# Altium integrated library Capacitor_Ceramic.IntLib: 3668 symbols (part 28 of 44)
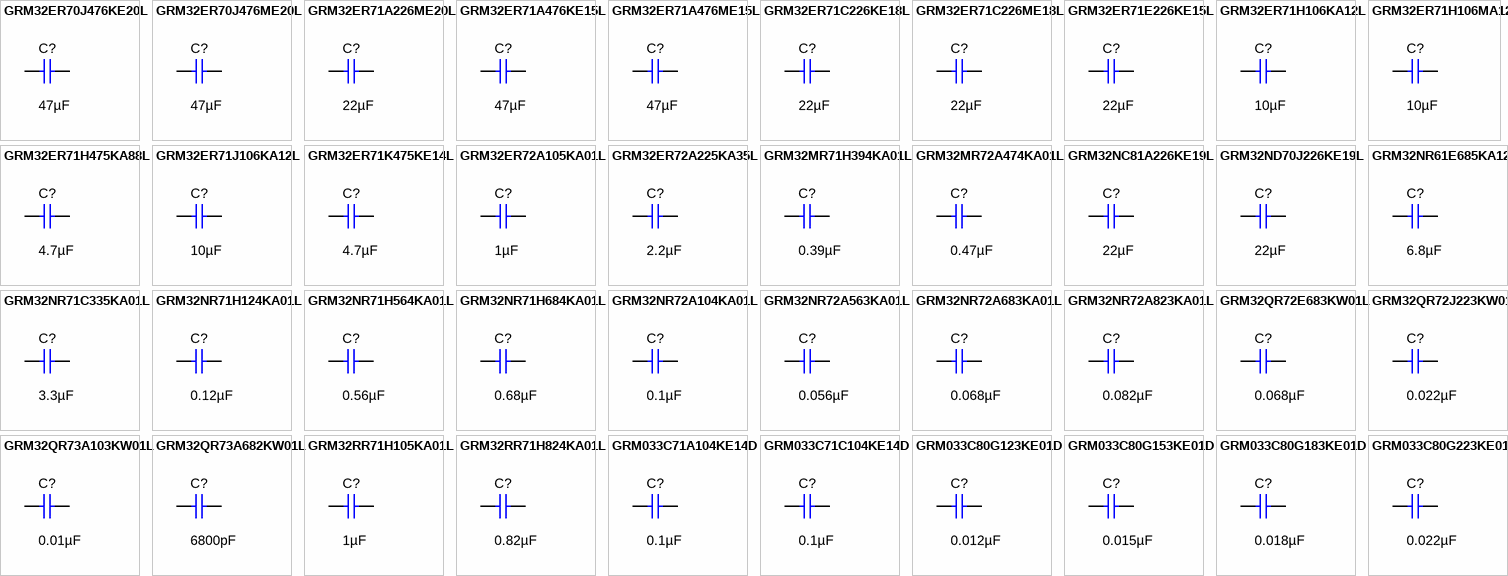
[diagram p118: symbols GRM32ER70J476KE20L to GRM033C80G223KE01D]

## GRM32ER71A476KE15L
designator C?  ValueDisplayed: 47µF  (hidden comment: GRM32ER71A476KE15L)
CAP, CERM, 47 µF, 10 V,+/- 10%, X7R, 1210; Manufacturer: MuRata; Polarized: N; CompType: Capacitor; Value: 47uF; U/M: EA; Cap_F: 0.000047; Tolerance_%: 10; Value2: 10V; TaMin_C: -55; TaMax_C: 125; Cap_Case: 1210; SizeArea_mm2: 8; SizeAreaWB_mm2: 14.7; SizeX_mm: 3.2; SizeY_mm: 2.5; SizeZ_mm: 2.7; AEC Category: Q200; Green_Lifecycle: Active; Green_REACh: Passed
signal-integrity model Cap
simulation model Cap
footprint 1210_270
footprint 1210_270M
footprint 1210_270L
pins: 1, 2

## GRM32ER71A476ME15L
designator C?  ValueDisplayed: 47µF  (hidden comment: GRM32ER71A476ME15L)
CAP, CERM, 47 µF, 10 V,+/- 20%, X7R, 1210; Manufacturer: MuRata; Polarized: N; CompType: Capacitor; Value: 47uF; U/M: EA; Cap_F: 0.000047; Tolerance_%: 20; VDC_V: 10; Value2: 10V; TaMin_C: -55; TaMax_C: 125; Cap_Case: 1210; SizeArea_mm2: 8; SizeAreaWB_mm2: 14.7; SizeX_mm: 3.2; SizeY_mm: 2.5; SizeZ_mm: 2.7; AEC Category: Q200; Green_Lifecycle: Active; Green_REACh: Passed
signal-integrity model Cap
simulation model Cap
footprint 1210_270
footprint 1210_270M
footprint 1210_270L
pins: 1, 2

## GRM32ER71C226KE18L
designator C?  ValueDisplayed: 22µF  (hidden comment: GRM32ER71C226KE18L)
CAP, CERM, 22 µF, 16 V,+/- 10%, X7R, 1210; Manufacturer: MuRata; Polarized: N; CompType: Capacitor; Value: 22uF; U/M: EA; Cap_F: 0.000022; Tolerance_%: 10; ESR_ohm: 0.003; Value1: 0.003 ohm; VDC_V: 16; Value2: 16V; TaMin_C: -55; TaMax_C: 125; Cap_Case: 1210; SizeArea_mm2: 8; SizeAreaWB_mm2: 14.7; SizeX_mm: 3.2; SizeY_mm: 2.5; SizeZ_mm: 2.7; AEC Category: Q200; Green_Lifecycle: Not Set; Green_REACh: Incomplete
signal-integrity model Cap
simulation model Cap
footprint 1210_270
footprint 1210_270M
footprint 1210_270L
pins: 1, 2

## GRM32ER71C226ME18L
designator C?  ValueDisplayed: 22µF  (hidden comment: GRM32ER71C226ME18L)
CAP, CERM, 22 µF, 16 V,+/- 20%, X7R, 1210; Manufacturer: MuRata; Polarized: N; CompType: Capacitor; Value: 22uF; U/M: EA; Cap_F: 0.000022; Tolerance_%: 20; ESR_ohm: 0.003; Value1: 0.003 ohm; VDC_V: 16; Value2: 16V; IRMS_A: 3.2; TaMin_C: -55; TaMax_C: 125; Cap_Case: 1210; SizeArea_mm2: 8; SizeAreaWB_mm2: 14.7; SizeY_mm: 2.5; SizeZ_mm: 2.7; AEC Category: Q200; Green_Lifecycle: Not Set; Green_REACh: Incomplete
signal-integrity model Cap
simulation model Cap
footprint 1210_270
footprint 1210_270M
footprint 1210_270L
pins: 1, 2

## GRM32ER71E226KE15L
designator C?  ValueDisplayed: 22µF  (hidden comment: GRM32ER71E226KE15L)
CAP, CERM, 22 µF, 25 V,+/- 10%, X7R, 1210; Manufacturer: MuRata; Polarized: N; CompType: Capacitor; Value: 22uF; U/M: EA; Cap_F: 0.000022; Tolerance_%: 10; ESR_ohm: 0.002334; Value1: 0.002334 ohm; VDC_V: 25; Value2: 25V; IRMS_A: 3.832999; TaMin_C: -55; TaMax_C: 125; Cap_Case: 1210; SizeArea_mm2: 8; SizeAreaWB_mm2: 14.7; SizeX_mm: 3.2; SizeY_mm: 2.5; SizeZ_mm: 2.7; AEC Category: Q200; Green_Lifecycle: Active; Green_REACh: Passed
signal-integrity model Cap
simulation model Cap
footprint 1210_270
footprint 1210_270M
footprint 1210_270L
pins: 1, 2

## GRM32ER71H106KA12L
designator C?  ValueDisplayed: 10µF  (hidden comment: GRM32ER71H106KA12L)
CAP, CERM, 10 µF, 50 V,+/- 10%, X7R, 1210; Manufacturer: MuRata; Polarized: N; CompType: Capacitor; Value: 10uF; U/M: EA; Cap_F: 0.00001; Tolerance_%: 10; VDC_V: 50; Value2: 50V; TaMin_C: -55; TaMax_C: 125; Cap_Case: 1210; SizeArea_mm2: 8; SizeAreaWB_mm2: 14.7; SizeX_mm: 3.2; SizeY_mm: 2.5; SizeZ_mm: 2.7; AEC Category: Q200; Green_Lifecycle: Active; Green_REACh: Passed
signal-integrity model Cap
simulation model Cap
footprint 1210_270
footprint 1210_270M
footprint 1210_270L
pins: 1, 2

## GRM32ER71H106MA12
designator C?  ValueDisplayed: 10µF  (hidden comment: GRM32ER71H106MA12)
CAP, CERM, 10 µF, 50 V,+/- 20%, X7R, 1210; Manufacturer: MuRata; Polarized: N; CompType: Capacitor; Value: 10uF; U/M: EA; Cap_F: 0.00001; Tolerance_%: 20; VDC_V: 50; Value2: 50V; TaMin_C: -55; TaMax_C: 125; Cap_Case: 1210; SizeArea_mm2: 8; SizeAreaWB_mm2: 14.7; SizeX_mm: 3.2; SizeY_mm: 2.5; SizeZ_mm: 2.7; AEC Category: Q200
signal-integrity model Cap
simulation model Cap
footprint 1210_270
footprint 1210_270M
footprint 1210_270L
pins: 1, 2

## GRM32ER71H475KA88L
designator C?  ValueDisplayed: 4.7µF  (hidden comment: GRM32ER71H475KA88L)
CAP, CERM, 4.7 µF, 50 V,+/- 10%, X7R, 1210; Manufacturer: MuRata; Polarized: N; CompType: Capacitor; Value: 4.7uF; U/M: EA; Cap_F: 0.0000047; Tolerance_%: 10; ESR_ohm: 0.002; Value1: 0.002 ohm; VDC_V: 50; Value2: 50V; TaMin_C: -55; TaMax_C: 125; Cap_Case: 1210; SizeArea_mm2: 8; SizeAreaWB_mm2: 14.7; SizeX_mm: 3.2; SizeY_mm: 2.5; SizeZ_mm: 2.7; AEC Category: Q200; Green_Lifecycle: Active; Green_REACh: Passed
signal-integrity model Cap
simulation model Cap
footprint 1210_270
footprint 1210_270M
footprint 1210_270L
pins: 1, 2

## GRM32ER71J106KA12L
designator C?  ValueDisplayed: 10µF  (hidden comment: GRM32ER71J106KA12L)
CAP, CERM, 10 µF, 63 V,+/- 10%, X7R, 1210; Manufacturer: MuRata; Polarized: N; CompType: Capacitor; Value: 10uF; U/M: EA; Cap_F: 0.00001; Tolerance_%: 10; VDC_V: 63; Value2: 63V; TaMin_C: -55; TaMax_C: 125; Cap_Case: 1210; SizeArea_mm2: 8; SizeAreaWB_mm2: 14.7; SizeX_mm: 3.2; SizeY_mm: 2.5; SizeZ_mm: 2.7; AEC Category: Q200; Green_Lifecycle: Active; Green_REACh: Passed
signal-integrity model Cap
simulation model Cap
footprint 1210_270
footprint 1210_270M
footprint 1210_270L
pins: 1, 2

## GRM32ER71K475KE14L
designator C?  ValueDisplayed: 4.7µF  (hidden comment: GRM32ER71K475KE14L)
CAP, CERM, 4.7 µF, 80 V,+/- 10%, X7R, 1210; Manufacturer: MuRata; Polarized: N; CompType: Capacitor; Value: 4.7uF; U/M: EA; Cap_F: 0.0000047; Tolerance_%: 10; VDC_V: 80; Value2: 80V; TaMin_C: -55; TaMax_C: 125; Cap_Case: 1210; SizeArea_mm2: 8; SizeAreaWB_mm2: 14.7; SizeX_mm: 3.2; SizeY_mm: 2.5; SizeZ_mm: 2.7; AEC Category: Q200
signal-integrity model Cap
simulation model Cap
footprint 1210_270
footprint 1210_270M
footprint 1210_270L
pins: 1, 2

## GRM32ER72A105KA01L
designator C?  ValueDisplayed: 1µF  (hidden comment: GRM32ER72A105KA01L)
CAP, CERM, 1 µF, 100 V,+/- 10%, X7R, 1210; Manufacturer: MuRata; Polarized: N; CompType: Capacitor; Value: 1uF; U/M: EA; Cap_F: 0.000001; Tolerance_%: 10; VDC_V: 100; Value2: 100V; TaMin_C: -55; TaMax_C: 125; Cap_Case: 1210; SizeArea_mm2: 8; SizeAreaWB_mm2: 14.7; SizeX_mm: 3.2; SizeY_mm: 2.5; SizeZ_mm: 2.7; AEC Category: Q200; Green_Lifecycle: Active; Green_REACh: Passed
signal-integrity model Cap
simulation model Cap
footprint 1210_270
footprint 1210_270M
footprint 1210_270L
pins: 1, 2

## GRM32ER72A225KA35L
designator C?  ValueDisplayed: 2.2µF  (hidden comment: GRM32ER72A225KA35L)
CAP, CERM, 2.2 µF, 100 V,+/- 10%, X7R, 1210; Manufacturer: MuRata; Polarized: N; CompType: Capacitor; Value: 2.2uF; U/M: EA; Cap_F: 0.0000022; Tolerance_%: 10; ESR_ohm: 0.007; Value1: 0.007 ohm; VDC_V: 100; Value2: 100V; IRMS_A: 4.4; TaMin_C: -55; TaMax_C: 125; Cap_Case: 1210; SizeArea_mm2: 8; SizeAreaWB_mm2: 14.7; SizeX_mm: 3.2; SizeY_mm: 2.5; SizeZ_mm: 2.7; AEC Category: Q200; Green_Lifecycle: Active; Green_REACh: Passed
signal-integrity model Cap
simulation model Cap
footprint 1210_270
footprint 1210_270M
footprint 1210_270L
pins: 1, 2

## GRM32MR71H394KA01L
designator C?  ValueDisplayed: 0.39µF  (hidden comment: GRM32MR71H394KA01L)
CAP, CERM, 0.39 µF, 50 V,+/- 10%, X7R, 1210; Manufacturer: MuRata; Polarized: N; CompType: Capacitor; Value: 0.39uF; U/M: EA; Cap_F: 0.00000039; Tolerance_%: 10; VDC_V: 50; Value2: 50V; TaMin_C: -55; TaMax_C: 125; Cap_Case: 1210; SizeArea_mm2: 8; SizeAreaWB_mm2: 14.7; SizeX_mm: 3.2; SizeY_mm: 2.5; SizeZ_mm: 1.35; AEC Category: Q200
signal-integrity model Cap
simulation model Cap
footprint 1210
footprint 1210M
footprint 1210L
pins: 1, 2

## GRM32MR72A474KA01L
designator C?  ValueDisplayed: 0.47µF  (hidden comment: GRM32MR72A474KA01L)
CAP, CERM, 0.47 µF, 100 V,+/- 10%, X7R, 1210; Manufacturer: MuRata; Polarized: N; CompType: Capacitor; Value: 0.47uF; U/M: EA; Cap_F: 0.00000047; Tolerance_%: 10; VDC_V: 100; Value2: 100V; TaMin_C: -55; TaMax_C: 125; Cap_Case: 1210; SizeArea_mm2: 8; SizeAreaWB_mm2: 14.7; SizeX_mm: 3.2; SizeY_mm: 2.5; SizeZ_mm: 1.35; AEC Category: Q200
signal-integrity model Cap
simulation model Cap
footprint 1210
footprint 1210M
footprint 1210L
pins: 1, 2

## GRM32NC81A226KE19L
designator C?  ValueDisplayed: 22µF  (hidden comment: GRM32NC81A226KE19L)
CAP, CERM, 22 µF, 10 V,+/- 10%, X6S, 1210; Manufacturer: MuRata; Polarized: N; CompType: Capacitor; Value: 22uF; U/M: EA; Cap_F: 0.000022; Tolerance_%: 10; Value2: 10V; TaMin_C: -55; TaMax_C: 105; Cap_Case: 1210; SizeArea_mm2: 8; SizeAreaWB_mm2: 14.7; SizeX_mm: 3.2; SizeY_mm: 2.5; SizeZ_mm: 1.5; AEC Category: Q200
signal-integrity model Cap
simulation model Cap
footprint 1210_150
footprint 1210_150M
footprint 1210_150L
pins: 1, 2

## GRM32ND70J226KE19L
designator C?  ValueDisplayed: 22µF  (hidden comment: GRM32ND70J226KE19L)
CAP, CERM, 22 µF, 6.3 V,+/- 10%, X7T, 1210; Manufacturer: MuRata; Polarized: N; CompType: Capacitor; Value: 22uF; U/M: EA; Cap_F: 0.000022; Tolerance_%: 10; VDC_V: 6.3; Value2: 6.3V; TaMin_C: -55; TaMax_C: 125; Cap_Case: 1210; SizeArea_mm2: 8; SizeAreaWB_mm2: 14.7; SizeX_mm: 3.2; SizeY_mm: 2.5; SizeZ_mm: 1.5; AEC Category: Q200
signal-integrity model Cap
simulation model Cap
footprint 1210_150
footprint 1210_150M
footprint 1210_150L
pins: 1, 2

## GRM32NR61E685KA12L
designator C?  ValueDisplayed: 6.8µF  (hidden comment: GRM32NR61E685KA12L)
CAP, CERM, 6.8 µF, 25 V,+/- 10%, X5R, 1210; Manufacturer: MuRata; Polarized: N; CompType: Capacitor; Value: 6.8uF; U/M: EA; Cap_F: 0.0000068; Tolerance_%: 10; VDC_V: 25; Value2: 25V; TaMin_C: -55; TaMax_C: 85; Cap_Case: 1210; SizeArea_mm2: 8; SizeAreaWB_mm2: 14.7; SizeX_mm: 3.2; SizeY_mm: 2.5; SizeZ_mm: 1.5; AEC Category: Q200
signal-integrity model Cap
simulation model Cap
footprint 1210_150
footprint 1210_150M
footprint 1210_150L
pins: 1, 2

## GRM32NR71C335KA01L
designator C?  ValueDisplayed: 3.3µF  (hidden comment: GRM32NR71C335KA01L)
CAP, CERM, 3.3 µF, 16 V,+/- 10%, X7R, 1210; Manufacturer: MuRata; Polarized: N; CompType: Capacitor; Value: 3.3uF; U/M: EA; Cap_F: 0.0000033; Tolerance_%: 10; VDC_V: 16; Value2: 16V; TaMin_C: -55; TaMax_C: 125; Cap_Case: 1210; SizeArea_mm2: 8; SizeAreaWB_mm2: 14.7; SizeX_mm: 3.2; SizeY_mm: 2.5; SizeZ_mm: 1.5; AEC Category: Q200
signal-integrity model Cap
simulation model Cap
footprint 1210_150
footprint 1210_150M
footprint 1210_150L
pins: 1, 2

## GRM32NR71H124KA01L
designator C?  ValueDisplayed: 0.12µF  (hidden comment: GRM32NR71H124KA01L)
CAP, CERM, 0.12 µF, 50 V,+/- 10%, X7R, 1210; Manufacturer: MuRata; Polarized: N; CompType: Capacitor; Value: 0.12uF; U/M: EA; Cap_F: 0.00000012; Tolerance_%: 10; VDC_V: 50; Value2: 50V; TaMin_C: -55; TaMax_C: 125; Cap_Case: 1210; SizeArea_mm2: 8; SizeAreaWB_mm2: 14.7; SizeX_mm: 3.2; SizeY_mm: 2.5; SizeZ_mm: 1.5; AEC Category: Q200
signal-integrity model Cap
simulation model Cap
footprint 1210_150
footprint 1210_150M
footprint 1210_150L
pins: 1, 2

## GRM32NR71H564KA01L
designator C?  ValueDisplayed: 0.56µF  (hidden comment: GRM32NR71H564KA01L)
CAP, CERM, 0.56 µF, 50 V,+/- 10%, X7R, 1210; Manufacturer: MuRata; Polarized: N; CompType: Capacitor; Value: 0.56uF; U/M: EA; Cap_F: 0.00000056; Tolerance_%: 10; VDC_V: 50; Value2: 50V; TaMin_C: -55; TaMax_C: 125; Cap_Case: 1210; SizeArea_mm2: 8; SizeAreaWB_mm2: 14.7; SizeX_mm: 3.2; SizeY_mm: 2.5; SizeZ_mm: 1.5; AEC Category: Q200
signal-integrity model Cap
simulation model Cap
footprint 1210_150
footprint 1210_150M
footprint 1210_150L
pins: 1, 2

## GRM32NR71H684KA01L
designator C?  ValueDisplayed: 0.68µF  (hidden comment: GRM32NR71H684KA01L)
CAP, CERM, 0.68 µF, 50 V,+/- 10%, X7R, 1210; Manufacturer: MuRata; Polarized: N; CompType: Capacitor; Value: 0.68uF; U/M: EA; Cap_F: 0.00000068; Tolerance_%: 10; VDC_V: 50; Value2: 50V; TaMin_C: -55; TaMax_C: 125; Cap_Case: 1210; SizeArea_mm2: 8; SizeAreaWB_mm2: 14.7; SizeX_mm: 3.2; SizeY_mm: 2.5; SizeZ_mm: 1.5; AEC Category: Q200
signal-integrity model Cap
simulation model Cap
footprint 1210_150
footprint 1210_150M
footprint 1210_150L
pins: 1, 2

## GRM32NR72A104KA01L
designator C?  ValueDisplayed: 0.1µF  (hidden comment: GRM32NR72A104KA01L)
CAP, CERM, 0.1 µF, 100 V,+/- 10%, X7R, 1210; Manufacturer: MuRata; Polarized: N; CompType: Capacitor; Value: 0.1uF; U/M: EA; Cap_F: 0.0000001; Tolerance_%: 10; VDC_V: 100; Value2: 100V; TaMin_C: -55; TaMax_C: 125; Cap_Case: 1210; SizeArea_mm2: 8; SizeAreaWB_mm2: 14.7; SizeX_mm: 3.2; SizeY_mm: 2.5; SizeZ_mm: 1.5; AEC Category: Q200; Green_Lifecycle: Active; Green_REACh: Passed
signal-integrity model Cap
simulation model Cap
footprint 1210_150
footprint 1210_150M
footprint 1210_150L
pins: 1, 2

## GRM32NR72A563KA01L
designator C?  ValueDisplayed: 0.056µF  (hidden comment: GRM32NR72A563KA01L)
CAP, CERM, 0.056 µF, 100 V,+/- 10%, X7R, 1210; Manufacturer: MuRata; Polarized: N; CompType: Capacitor; Value: 0.056uF; U/M: EA; Cap_F: 0.000000056; Tolerance_%: 10; VDC_V: 100; Value2: 100V; TaMin_C: -55; TaMax_C: 125; Cap_Case: 1210; SizeArea_mm2: 8; SizeAreaWB_mm2: 14.7; SizeX_mm: 3.2; SizeY_mm: 2.5; SizeZ_mm: 1.5; AEC Category: Q200
signal-integrity model Cap
simulation model Cap
footprint 1210_150
footprint 1210_150M
footprint 1210_150L
pins: 1, 2

## GRM32NR72A683KA01L
designator C?  ValueDisplayed: 0.068µF  (hidden comment: GRM32NR72A683KA01L)
CAP, CERM, 0.068 µF, 100 V,+/- 10%, X7R, 1210; Manufacturer: MuRata; Polarized: N; CompType: Capacitor; Value: 0.068uF; U/M: EA; Cap_F: 0.000000068; Tolerance_%: 10; VDC_V: 100; Value2: 100V; TaMin_C: -55; TaMax_C: 125; Cap_Case: 1210; SizeArea_mm2: 8; SizeAreaWB_mm2: 14.7; SizeX_mm: 3.2; SizeY_mm: 2.5; SizeZ_mm: 1.5; AEC Category: Q200
signal-integrity model Cap
simulation model Cap
footprint 1210_150
footprint 1210_150M
footprint 1210_150L
pins: 1, 2

## GRM32NR72A823KA01L
designator C?  ValueDisplayed: 0.082µF  (hidden comment: GRM32NR72A823KA01L)
CAP, CERM, 0.082 µF, 100 V,+/- 10%, X7R, 1210; Manufacturer: MuRata; Polarized: N; CompType: Capacitor; Value: 0.082uF; U/M: EA; Cap_F: 0.000000082; Tolerance_%: 10; VDC_V: 100; Value2: 100V; TaMin_C: -55; TaMax_C: 125; Cap_Case: 1210; SizeArea_mm2: 8; SizeAreaWB_mm2: 14.7; SizeX_mm: 3.2; SizeY_mm: 2.5; SizeZ_mm: 1.5; AEC Category: Q200
signal-integrity model Cap
simulation model Cap
footprint 1210_150
footprint 1210_150M
footprint 1210_150L
pins: 1, 2

## GRM32QR72E683KW01L
designator C?  ValueDisplayed: 0.068µF  (hidden comment: GRM32QR72E683KW01L)
CAP, CERM, 0.068 µF, 250 V,+/- 10%, X7R, 1210; Manufacturer: MuRata; Polarized: N; CompType: Capacitor; Value: 0.068uF; U/M: EA; Cap_F: 0.000000068; Tolerance_%: 10; VDC_V: 250; Value2: 250V; TaMin_C: -55; TaMax_C: 125; Cap_Case: 1210; SizeArea_mm2: 8; SizeAreaWB_mm2: 14.7; SizeX_mm: 3.2; SizeY_mm: 2.5; SizeZ_mm: 1.5; AEC Category: Q200
signal-integrity model Cap
simulation model Cap
footprint 1210_150
footprint 1210_150M
footprint 1210_150L
pins: 1, 2

## GRM32QR72J223KW01L
designator C?  ValueDisplayed: 0.022µF  (hidden comment: GRM32QR72J223KW01L)
CAP, CERM, 0.022 µF, 630 V,+/- 10%, X7R, 1210; Manufacturer: MuRata; Polarized: N; CompType: Capacitor; Value: 0.022uF; U/M: EA; Cap_F: 0.000000022; Tolerance_%: 10; VDC_V: 630; Value2: 630V; TaMin_C: -55; TaMax_C: 125; Cap_Case: 1210; SizeArea_mm2: 8; SizeAreaWB_mm2: 14.7; SizeX_mm: 3.2; SizeY_mm: 2.5; SizeZ_mm: 1.5; AEC Category: Q200
signal-integrity model Cap
simulation model Cap
footprint 1210_150
footprint 1210_150M
footprint 1210_150L
pins: 1, 2

## GRM32QR73A103KW01L
designator C?  ValueDisplayed: 0.01µF  (hidden comment: GRM32QR73A103KW01L)
CAP, CERM, 0.01 µF, 1000 V,+/- 10%, X7R, 1210; Manufacturer: MuRata; Polarized: N; CompType: Capacitor; Value: 0.01uF; U/M: EA; Cap_F: 0.00000001; Tolerance_%: 10; VDC_V: 1000; Value2: 1000V; TaMin_C: -55; TaMax_C: 125; Cap_Case: 1210; SizeArea_mm2: 8; SizeAreaWB_mm2: 14.7; SizeX_mm: 3.2; SizeY_mm: 2.5; SizeZ_mm: 1.5; AEC Category: Q200
signal-integrity model Cap
simulation model Cap
footprint 1210_150
footprint 1210_150M
footprint 1210_150L
pins: 1, 2

## GRM32QR73A682KW01L
designator C?  ValueDisplayed: 6800pF  (hidden comment: GRM32QR73A682KW01L)
CAP, CERM, 6800 pF, 1000 V,+/- 10%, X7R, 1210; Manufacturer: MuRata; Polarized: N; CompType: Capacitor; Value: 6800pF; U/M: EA; Cap_F: 0.0000000068; Tolerance_%: 10; VDC_V: 1000; Value2: 1000V; TaMin_C: -55; TaMax_C: 125; Cap_Case: 1210; SizeArea_mm2: 8; SizeAreaWB_mm2: 14.7; SizeX_mm: 3.2; SizeY_mm: 2.5; SizeZ_mm: 1.5; AEC Category: Q200
signal-integrity model Cap
simulation model Cap
footprint 1210_150
footprint 1210_150M
footprint 1210_150L
pins: 1, 2

## GRM32RR71H105KA01L
designator C?  ValueDisplayed: 1µF  (hidden comment: GRM32RR71H105KA01L)
CAP, CERM, 1 µF, 50 V,+/- 10%, X7R, 1210; Manufacturer: MuRata; Polarized: N; CompType: Capacitor; Value: 1uF; U/M: EA; Cap_F: 0.000001; Tolerance_%: 10; ESR_ohm: 0.003; Value1: 0.003 ohm; VDC_V: 50; Value2: 50V; TaMin_C: -55; TaMax_C: 125; Cap_Case: 1210; SizeArea_mm2: 8; SizeAreaWB_mm2: 14.7; SizeX_mm: 3.2; SizeY_mm: 2.5; SizeZ_mm: 2; AEC Category: Q200; Green_Lifecycle: Active; Green_REACh: Passed
signal-integrity model Cap
simulation model Cap
footprint 1210_200
footprint 1210_200M
footprint 1210_200L
pins: 1, 2

## GRM32RR71H824KA01L
designator C?  ValueDisplayed: 0.82µF  (hidden comment: GRM32RR71H824KA01L)
CAP, CERM, 0.82 µF, 50 V,+/- 10%, X7R, 1210; Manufacturer: MuRata; Polarized: N; CompType: Capacitor; Value: 0.82uF; U/M: EA; Cap_F: 0.00000082; Tolerance_%: 10; VDC_V: 50; Value2: 50V; TaMin_C: -30; TaMax_C: 85; Cap_Case: 1210; SizeArea_mm2: 8; SizeAreaWB_mm2: 14.7; SizeX_mm: 3.2; SizeY_mm: 2.5; SizeZ_mm: 2; AEC Category: Q200
signal-integrity model Cap
simulation model Cap
footprint 1210_200
footprint 1210_200M
footprint 1210_200L
pins: 1, 2

## GRM033C71A104KE14D
designator C?  ValueDisplayed: 0.1µF  (hidden comment: GRM033C71A104KE14D)
CAP, CERM, 0.1 µF, 10 V,+/- 10%, X7S, 0201; Manufacturer: MuRata; Polarized: N; CompType: Capacitor; Value: 0.1uF; U/M: EA; Cap_F: 0.0000001; Tolerance_%: 10; Value2: 10V; TaMin_C: -55; TaMax_C: 125; Cap_Case: 0201; SizeArea_mm2: 0.18; SizeAreaWB_mm2: 2.08; SizeX_mm: 0.6; SizeY_mm: 0.3; SizeZ_mm: 0.26; AEC Category: Q200
signal-integrity model Cap
simulation model Cap
footprint 0201
footprint 0201M
footprint 0201L
footprint 0201_Silk
pins: 1, 2

## GRM033C71C104KE14D
designator C?  ValueDisplayed: 0.1µF  (hidden comment: GRM033C71C104KE14D)
CAP, CERM, 0.1 µF, 16 V,+/- 10%, X5R, 0201; Manufacturer: MuRata; Polarized: N; CompType: Capacitor; Value: 0.1uF; U/M: EA; Cap_F: 0.0000001; Tolerance_%: 10; VDC_V: 16; Value2: 16V; TaMin_C: -55; TaMax_C: 125; Cap_Case: 0201; SizeArea_mm2: 0.18; SizeAreaWB_mm2: 2.08; SizeX_mm: 0.6; SizeY_mm: 0.3; SizeZ_mm: 0.33; AEC Category: Q200
signal-integrity model Cap
simulation model Cap
footprint 0201_033
footprint 0201_033M
footprint 0201_033L
pins: 1, 2

## GRM033C80G123KE01D
designator C?  ValueDisplayed: 0.012µF  (hidden comment: GRM033C80G123KE01D)
CAP, CERM, 0.012 µF, 4 V,+/- 10%, X6S, 0201; Manufacturer: MuRata; Polarized: N; CompType: Capacitor; Value: 0.012uF; U/M: EA; Cap_F: 0.000000012; Tolerance_%: 10; VDC_V: 4; Value2: 4V; TaMin_C: -55; TaMax_C: 105; Cap_Case: 0201; SizeArea_mm2: 0.18; SizeAreaWB_mm2: 2.08; SizeX_mm: 0.6; SizeY_mm: 0.3; SizeZ_mm: 0.26; AEC Category: Q200
signal-integrity model Cap
simulation model Cap
footprint 0201
footprint 0201M
footprint 0201L
footprint 0201_Silk
pins: 1, 2

## GRM033C80G153KE01D
designator C?  ValueDisplayed: 0.015µF  (hidden comment: GRM033C80G153KE01D)
CAP, CERM, 0.015 µF, 4 V,+/- 10%, X6S, 0201; Manufacturer: MuRata; Polarized: N; CompType: Capacitor; Value: 0.015uF; U/M: EA; Cap_F: 0.000000015; Tolerance_%: 10; VDC_V: 4; Value2: 4V; TaMin_C: -55; TaMax_C: 105; Cap_Case: 0201; SizeArea_mm2: 0.18; SizeAreaWB_mm2: 2.08; SizeX_mm: 0.6; SizeY_mm: 0.3; SizeZ_mm: 0.26; AEC Category: Q200
signal-integrity model Cap
simulation model Cap
footprint 0201
footprint 0201M
footprint 0201L
footprint 0201_Silk
pins: 1, 2

## GRM033C80G183KE01D
designator C?  ValueDisplayed: 0.018µF  (hidden comment: GRM033C80G183KE01D)
CAP, CERM, 0.018 µF, 4 V,+/- 10%, X6S, 0201; Manufacturer: MuRata; Polarized: N; CompType: Capacitor; Value: 0.018uF; U/M: EA; Cap_F: 0.000000018; Tolerance_%: 10; VDC_V: 4; Value2: 4V; TaMin_C: -55; TaMax_C: 105; Cap_Case: 0201; SizeArea_mm2: 0.18; SizeAreaWB_mm2: 2.08; SizeX_mm: 0.6; SizeY_mm: 0.3; SizeZ_mm: 0.26; AEC Category: Q200
signal-integrity model Cap
simulation model Cap
footprint 0201
footprint 0201M
footprint 0201L
footprint 0201_Silk
pins: 1, 2

## GRM033C80G223KE01D
designator C?  ValueDisplayed: 0.022µF  (hidden comment: GRM033C80G223KE01D)
CAP, CERM, 0.022 µF, 4 V,+/- 10%, X6S, 0201; Manufacturer: MuRata; Polarized: N; CompType: Capacitor; Value: 0.022uF; U/M: EA; Cap_F: 0.000000022; Tolerance_%: 10; VDC_V: 4; Value2: 4V; TaMin_C: -55; TaMax_C: 105; Cap_Case: 0201; SizeArea_mm2: 0.18; SizeAreaWB_mm2: 2.08; SizeX_mm: 0.6; SizeY_mm: 0.3; SizeZ_mm: 0.26; AEC Category: Q200
signal-integrity model Cap
simulation model Cap
footprint 0201
footprint 0201M
footprint 0201L
footprint 0201_Silk
pins: 1, 2

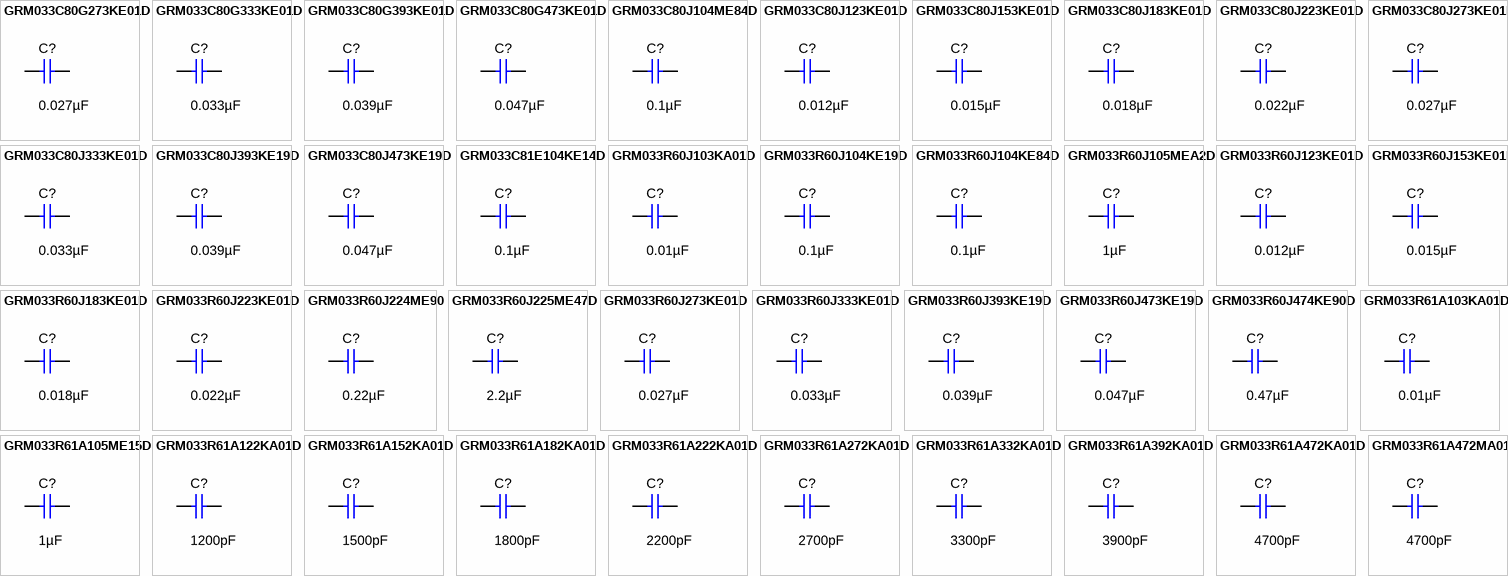
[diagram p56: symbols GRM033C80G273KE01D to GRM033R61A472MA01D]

## GRM033C80G273KE01D
designator C?  ValueDisplayed: 0.027µF  (hidden comment: GRM033C80G273KE01D)
CAP, CERM, 0.027 µF, 4 V,+/- 10%, X6S, 0201; Manufacturer: MuRata; Polarized: N; CompType: Capacitor; Value: 0.027uF; U/M: EA; Cap_F: 0.000000027; Tolerance_%: 10; VDC_V: 4; Value2: 4V; TaMin_C: -55; TaMax_C: 105; Cap_Case: 0201; SizeArea_mm2: 0.18; SizeAreaWB_mm2: 2.08; SizeX_mm: 0.6; SizeY_mm: 0.3; SizeZ_mm: 0.26; AEC Category: Q200
signal-integrity model Cap
simulation model Cap
footprint 0201
footprint 0201M
footprint 0201L
footprint 0201_Silk
pins: 1, 2

## GRM033C80G333KE01D
designator C?  ValueDisplayed: 0.033µF  (hidden comment: GRM033C80G333KE01D)
CAP, CERM, 0.033 µF, 4 V,+/- 10%, X6S, 0201; Manufacturer: MuRata; Polarized: N; CompType: Capacitor; Value: 0.033uF; U/M: EA; Cap_F: 0.000000033; Tolerance_%: 10; VDC_V: 4; Value2: 4V; TaMin_C: -55; TaMax_C: 105; Cap_Case: 0201; SizeArea_mm2: 0.18; SizeAreaWB_mm2: 2.08; SizeX_mm: 0.6; SizeY_mm: 0.3; SizeZ_mm: 0.26; AEC Category: Q200
signal-integrity model Cap
simulation model Cap
footprint 0201
footprint 0201M
footprint 0201L
footprint 0201_Silk
pins: 1, 2

## GRM033C80G393KE01D
designator C?  ValueDisplayed: 0.039µF  (hidden comment: GRM033C80G393KE01D)
CAP, CERM, 0.039 µF, 4 V,+/- 10%, X6S, 0201; Manufacturer: MuRata; Polarized: N; CompType: Capacitor; Value: 0.039uF; U/M: EA; Cap_F: 0.000000039; Tolerance_%: 10; VDC_V: 4; Value2: 4V; TaMin_C: -55; TaMax_C: 105; Cap_Case: 0201; SizeArea_mm2: 0.18; SizeAreaWB_mm2: 2.08; SizeX_mm: 0.6; SizeY_mm: 0.3; SizeZ_mm: 0.26; AEC Category: Q200
signal-integrity model Cap
simulation model Cap
footprint 0201
footprint 0201M
footprint 0201L
footprint 0201_Silk
pins: 1, 2

## GRM033C80G473KE01D
designator C?  ValueDisplayed: 0.047µF  (hidden comment: GRM033C80G473KE01D)
CAP, CERM, 0.047 µF, 4 V,+/- 10%, X6S, 0201; Manufacturer: MuRata; Polarized: N; CompType: Capacitor; Value: 0.047uF; U/M: EA; Cap_F: 0.000000047; Tolerance_%: 10; VDC_V: 4; Value2: 4V; TaMin_C: -55; TaMax_C: 105; Cap_Case: 0201; SizeArea_mm2: 0.18; SizeAreaWB_mm2: 2.08; SizeX_mm: 0.6; SizeY_mm: 0.3; SizeZ_mm: 0.26; AEC Category: Q200
signal-integrity model Cap
simulation model Cap
footprint 0201
footprint 0201M
footprint 0201L
footprint 0201_Silk
pins: 1, 2

## GRM033C80J104ME84D
designator C?  ValueDisplayed: 0.1µF  (hidden comment: GRM033C80J104ME84D)
CAP, CERM, 0.1 µF, 6.3 V,+/- 20%, X6S, 0201; Manufacturer: MuRata; Polarized: N; CompType: Capacitor; Value: 0.1uF; U/M: EA; Cap_F: 0.0000001; Tolerance_%: 20; VDC_V: 6.3; Value2: 6.3V; TaMin_C: -55; TaMax_C: 105; Cap_Case: 0201; SizeArea_mm2: 0.18; SizeAreaWB_mm2: 2.08; SizeX_mm: 0.6; SizeY_mm: 0.3; SizeZ_mm: 0.33; AEC Category: Q200
signal-integrity model Cap
simulation model Cap
footprint 0201_033
footprint 0201_033M
footprint 0201_033L
pins: 1, 2

## GRM033C80J123KE01D
designator C?  ValueDisplayed: 0.012µF  (hidden comment: GRM033C80J123KE01D)
CAP, CERM, 0.012 µF, 6.3 V,+/- 10%, X6S, 0201; Manufacturer: MuRata; Polarized: N; CompType: Capacitor; Value: 0.012uF; U/M: EA; Cap_F: 0.000000012; Tolerance_%: 10; VDC_V: 6.3; Value2: 6.3V; TaMin_C: -55; TaMax_C: 105; Cap_Case: 0201; SizeArea_mm2: 0.18; SizeAreaWB_mm2: 2.08; SizeX_mm: 0.6; SizeY_mm: 0.3; SizeZ_mm: 0.26; AEC Category: Q200
signal-integrity model Cap
simulation model Cap
footprint 0201
footprint 0201M
footprint 0201L
footprint 0201_Silk
pins: 1, 2

## GRM033C80J153KE01D
designator C?  ValueDisplayed: 0.015µF  (hidden comment: GRM033C80J153KE01D)
CAP, CERM, 0.015 µF, 6.3 V,+/- 10%, X6S, 0201; Manufacturer: MuRata; Polarized: N; CompType: Capacitor; Value: 0.015uF; U/M: EA; Cap_F: 0.000000015; Tolerance_%: 10; VDC_V: 6.3; Value2: 6.3V; TaMin_C: -55; TaMax_C: 105; Cap_Case: 0201; SizeArea_mm2: 0.18; SizeAreaWB_mm2: 2.08; SizeX_mm: 0.6; SizeY_mm: 0.3; SizeZ_mm: 0.26; AEC Category: Q200
signal-integrity model Cap
simulation model Cap
footprint 0201
footprint 0201M
footprint 0201L
footprint 0201_Silk
pins: 1, 2

## GRM033C80J183KE01D
designator C?  ValueDisplayed: 0.018µF  (hidden comment: GRM033C80J183KE01D)
CAP, CERM, 0.018 µF, 6.3 V,+/- 10%, X6S, 0201; Manufacturer: MuRata; Polarized: N; CompType: Capacitor; Value: 0.018uF; U/M: EA; Cap_F: 0.000000018; Tolerance_%: 10; VDC_V: 6.3; Value2: 6.3V; TaMin_C: -55; TaMax_C: 105; Cap_Case: 0201; SizeArea_mm2: 0.18; SizeAreaWB_mm2: 2.08; SizeX_mm: 0.6; SizeY_mm: 0.3; SizeZ_mm: 0.26; AEC Category: Q200
signal-integrity model Cap
simulation model Cap
footprint 0201
footprint 0201M
footprint 0201L
footprint 0201_Silk
pins: 1, 2

## GRM033C80J223KE01D
designator C?  ValueDisplayed: 0.022µF  (hidden comment: GRM033C80J223KE01D)
CAP, CERM, 0.022 µF, 6.3 V,+/- 10%, X6S, 0201; Manufacturer: MuRata; Polarized: N; CompType: Capacitor; Value: 0.022uF; U/M: EA; Cap_F: 0.000000022; Tolerance_%: 10; VDC_V: 6.3; Value2: 6.3V; TaMin_C: -55; TaMax_C: 105; Cap_Case: 0201; SizeArea_mm2: 0.18; SizeAreaWB_mm2: 2.08; SizeX_mm: 0.6; SizeY_mm: 0.3; SizeZ_mm: 0.26; AEC Category: Q200
signal-integrity model Cap
simulation model Cap
footprint 0201
footprint 0201M
footprint 0201L
footprint 0201_Silk
pins: 1, 2

## GRM033C80J273KE01D
designator C?  ValueDisplayed: 0.027µF  (hidden comment: GRM033C80J273KE01D)
CAP, CERM, 0.027 µF, 6.3 V,+/- 10%, X6S, 0201; Manufacturer: MuRata; Polarized: N; CompType: Capacitor; Value: 0.027uF; U/M: EA; Cap_F: 0.000000027; Tolerance_%: 10; VDC_V: 6.3; Value2: 6.3V; TaMin_C: -55; TaMax_C: 105; Cap_Case: 0201; SizeArea_mm2: 0.18; SizeAreaWB_mm2: 2.08; SizeX_mm: 0.6; SizeY_mm: 0.3; SizeZ_mm: 0.26; AEC Category: Q200
signal-integrity model Cap
simulation model Cap
footprint 0201
footprint 0201M
footprint 0201L
footprint 0201_Silk
pins: 1, 2

## GRM033C80J333KE01D
designator C?  ValueDisplayed: 0.033µF  (hidden comment: GRM033C80J333KE01D)
CAP, CERM, 0.033 µF, 6.3 V,+/- 10%, X6S, 0201; Manufacturer: MuRata; Polarized: N; CompType: Capacitor; Value: 0.033uF; U/M: EA; Cap_F: 0.000000033; Tolerance_%: 10; VDC_V: 6.3; Value2: 6.3V; TaMin_C: -55; TaMax_C: 105; Cap_Case: 0201; SizeArea_mm2: 0.18; SizeAreaWB_mm2: 2.08; SizeX_mm: 0.6; SizeY_mm: 0.3; SizeZ_mm: 0.26; AEC Category: Q200
signal-integrity model Cap
simulation model Cap
footprint 0201
footprint 0201M
footprint 0201L
footprint 0201_Silk
pins: 1, 2

## GRM033C80J393KE19D
designator C?  ValueDisplayed: 0.039µF  (hidden comment: GRM033C80J393KE19D)
CAP, CERM, 0.039 µF, 6.3 V,+/- 10%, X6S, 0201; Manufacturer: MuRata; Polarized: N; CompType: Capacitor; Value: 0.039uF; U/M: EA; Cap_F: 0.000000039; Tolerance_%: 10; VDC_V: 6.3; Value2: 6.3V; TaMin_C: -55; TaMax_C: 105; Cap_Case: 0201; SizeArea_mm2: 0.18; SizeAreaWB_mm2: 2.08; SizeX_mm: 0.6; SizeY_mm: 0.3; SizeZ_mm: 0.26; AEC Category: Q200
signal-integrity model Cap
simulation model Cap
footprint 0201
footprint 0201M
footprint 0201L
footprint 0201_Silk
pins: 1, 2

## GRM033C80J473KE19D
designator C?  ValueDisplayed: 0.047µF  (hidden comment: GRM033C80J473KE19D)
CAP, CERM, 0.047 µF, 6.3 V,+/- 10%, X6S, 0201; Manufacturer: MuRata; Polarized: N; CompType: Capacitor; Value: 0.047uF; U/M: EA; Cap_F: 0.000000047; Tolerance_%: 10; VDC_V: 6.3; Value2: 6.3V; TaMin_C: -55; TaMax_C: 105; Cap_Case: 0201; SizeArea_mm2: 0.18; SizeAreaWB_mm2: 2.08; SizeX_mm: 0.6; SizeY_mm: 0.3; SizeZ_mm: 0.26; AEC Category: Q200
signal-integrity model Cap
simulation model Cap
footprint 0201
footprint 0201M
footprint 0201L
footprint 0201_Silk
pins: 1, 2

## GRM033C81E104KE14D
designator C?  ValueDisplayed: 0.1µF  (hidden comment: GRM033C81E104KE14D)
CAP, CERM, 0.1 µF, 25 V,+/- 10%, X6S, 0201; Manufacturer: MuRata; Polarized: N; CompType: Capacitor; Value: 0.1uF; U/M: EA; Cap_F: 0.0000001; Tolerance_%: 10; VDC_V: 25; Value2: 25V; TaMin_C: -55; TaMax_C: 105; Cap_Case: 0201; SizeArea_mm2: 0.18; SizeAreaWB_mm2: 2.08; SizeX_mm: 0.6; SizeY_mm: 0.3; SizeZ_mm: 0.33; AEC Category: Q200
signal-integrity model Cap
simulation model Cap
footprint 0201_033
footprint 0201_033M
footprint 0201_033L
pins: 1, 2

## GRM033R60J103KA01D
designator C?  ValueDisplayed: 0.01µF  (hidden comment: GRM033R60J103KA01D)
CAP, CERM, 0.01 µF, 6.3 V,+/- 10%, X5R, 0201; Manufacturer: MuRata; Polarized: N; CompType: Capacitor; Value: 0.01uF; U/M: EA; Cap_F: 0.00000001; Tolerance_%: 10; VDC_V: 6.3; Value2: 6.3V; TaMin_C: -55; TaMax_C: 85; Cap_Case: 0201; SizeArea_mm2: 0.18; SizeAreaWB_mm2: 2.08; SizeX_mm: 0.6; SizeY_mm: 0.3; SizeZ_mm: 0.26; AEC Category: Q200; Green_Lifecycle: Active; Green_REACh: Passed
signal-integrity model Cap
simulation model Cap
footprint 0201
footprint 0201M
footprint 0201L
footprint 0201_Silk
pins: 1, 2

## GRM033R60J104KE19D
designator C?  ValueDisplayed: 0.1µF  (hidden comment: GRM033R60J104KE19D)
CAP, CERM, 0.1 µF, 6.3 V,+/- 10%, X5R, 0201; Manufacturer: MuRata; Polarized: N; CompType: Capacitor; Value: 0.1uF; U/M: EA; Cap_F: 0.0000001; Tolerance_%: 10; VDC_V: 6.3; Value2: 6.3V; TaMin_C: -55; TaMax_C: 85; Cap_Case: 0201; SizeArea_mm2: 0.18; SizeAreaWB_mm2: 2.08; SizeX_mm: 0.6; SizeY_mm: 0.3; SizeZ_mm: 0.33; AEC Category: Q200; Green_Lifecycle: Active; Green_REACh: Passed
signal-integrity model Cap
simulation model Cap
footprint 0201_033
footprint 0201_033M
footprint 0201_033L
pins: 1, 2

## GRM033R60J104KE84D
designator C?  ValueDisplayed: 0.1µF  (hidden comment: GRM033R60J104KE84D)
CAP, CERM, 0.1 µF, 6.3 V,+/- 10%, X5R, 0201; Manufacturer: MuRata; Polarized: N; CompType: Capacitor; Value: 0.1uF; U/M: EA; Cap_F: 0.0000001; Tolerance_%: 10; VDC_V: 6.3; Value2: 6.3V; TaMin_C: -55; TaMax_C: 85; Cap_Case: 0201; SizeArea_mm2: 0.18; SizeAreaWB_mm2: 2.08; SizeX_mm: 0.6; SizeY_mm: 0.3; SizeZ_mm: 0.33; AEC Category: Q200
signal-integrity model Cap
simulation model Cap
footprint 0201_033
footprint 0201_033M
footprint 0201_033L
pins: 1, 2

## GRM033R60J105MEA2D
designator C?  ValueDisplayed: 1µF  (hidden comment: GRM033R60J105MEA2D)
CAP, CERM, 1 µF, 6.3 V,+/- 20%, X5R, 0201; Manufacturer: MuRata; Polarized: N; CompType: Capacitor; Value: 1uF; U/M: EA; Cap_F: 0.000001; Tolerance_%: 20; VDC_V: 6.3; Value2: 6.3V; TaMin_C: -55; TaMax_C: 85; Cap_Case: 0201; SizeArea_mm2: 0.18; SizeAreaWB_mm2: 2.08; SizeX_mm: 0.6; SizeY_mm: 0.3; SizeZ_mm: 0.33; AEC Category: Q200; Green_Lifecycle: Active; Green_REACh: Passed
signal-integrity model Cap
simulation model Cap
footprint 0201_033
footprint 0201_033M
footprint 0201_033L
pins: 1, 2

## GRM033R60J123KE01D
designator C?  ValueDisplayed: 0.012µF  (hidden comment: GRM033R60J123KE01D)
CAP, CERM, 0.012 µF, 6.3 V,+/- 10%, X5R, 0201; Manufacturer: MuRata; Polarized: N; CompType: Capacitor; Value: 0.012uF; U/M: EA; Cap_F: 0.000000012; Tolerance_%: 10; VDC_V: 6.3; Value2: 6.3V; TaMin_C: -55; TaMax_C: 85; Cap_Case: 0201; SizeArea_mm2: 0.18; SizeAreaWB_mm2: 2.08; SizeX_mm: 0.6; SizeY_mm: 0.3; SizeZ_mm: 0.26; AEC Category: Q200
signal-integrity model Cap
simulation model Cap
footprint 0201
footprint 0201M
footprint 0201L
footprint 0201_Silk
pins: 1, 2

## GRM033R60J153KE01D
designator C?  ValueDisplayed: 0.015µF  (hidden comment: GRM033R60J153KE01D)
CAP, CERM, 0.015 µF, 6.3 V,+/- 10%, X5R, 0201; Manufacturer: MuRata; Polarized: N; CompType: Capacitor; Value: 0.015uF; U/M: EA; Cap_F: 0.000000015; Tolerance_%: 10; VDC_V: 6.3; Value2: 6.3V; TaMin_C: -55; TaMax_C: 85; Cap_Case: 0201; SizeArea_mm2: 0.18; SizeAreaWB_mm2: 2.08; SizeX_mm: 0.6; SizeY_mm: 0.3; SizeZ_mm: 0.26; AEC Category: Q200
signal-integrity model Cap
simulation model Cap
footprint 0201
footprint 0201M
footprint 0201L
footprint 0201_Silk
pins: 1, 2

## GRM033R60J183KE01D
designator C?  ValueDisplayed: 0.018µF  (hidden comment: GRM033R60J183KE01D)
CAP, CERM, 0.018 µF, 6.3 V,+/- 10%, X5R, 0201; Manufacturer: MuRata; Polarized: N; CompType: Capacitor; Value: 0.018uF; U/M: EA; Cap_F: 0.000000018; Tolerance_%: 10; VDC_V: 6.3; Value2: 6.3V; TaMin_C: -55; TaMax_C: 85; Cap_Case: 0201; SizeArea_mm2: 0.18; SizeAreaWB_mm2: 2.08; SizeX_mm: 0.6; SizeY_mm: 0.3; SizeZ_mm: 0.26; AEC Category: Q200
signal-integrity model Cap
simulation model Cap
footprint 0201
footprint 0201M
footprint 0201L
footprint 0201_Silk
pins: 1, 2

## GRM033R60J223KE01D
designator C?  ValueDisplayed: 0.022µF  (hidden comment: GRM033R60J223KE01D)
CAP, CERM, 0.022 µF, 6.3 V,+/- 10%, X5R, 0201; Manufacturer: MuRata; Polarized: N; CompType: Capacitor; Value: 0.022uF; U/M: EA; Cap_F: 0.000000022; Tolerance_%: 10; VDC_V: 6.3; Value2: 6.3V; TaMin_C: -55; TaMax_C: 85; Cap_Case: 0201; SizeArea_mm2: 0.18; SizeAreaWB_mm2: 2.08; SizeX_mm: 0.6; SizeY_mm: 0.3; SizeZ_mm: 0.26; AEC Category: Q200
signal-integrity model Cap
simulation model Cap
footprint 0201
footprint 0201M
footprint 0201L
footprint 0201_Silk
pins: 1, 2

## GRM033R60J224ME90
designator C?  ValueDisplayed: 0.22µF  (hidden comment: GRM033R60J224ME90)
CAP, CERM, 0.22 µF, 6.3 V,+/- 20%, X5R, 0201; Manufacturer: MuRata; Polarized: N; CompType: Capacitor; Value: 0.22uF; U/M: EA; Cap_F: 0.00000022; Tolerance_%: 20; VDC_V: 6.3; Value2: 6.3V; TaMin_C: -55; TaMax_C: 85; Cap_Case: 0201; SizeArea_mm2: 0.18; SizeAreaWB_mm2: 2.08; SizeX_mm: 0.6; SizeY_mm: 0.3; SizeZ_mm: 0.26; AEC Category: Q200; Green_Lifecycle: Active; Green_REACh: Passed
signal-integrity model Cap
simulation model Cap
footprint 0201
footprint 0201M
footprint 0201L
footprint 0201_Silk
pins: 1, 2

## GRM033R60J225ME47D
designator C?  ValueDisplayed: 2.2µF  (hidden comment: GRM033R60J225ME47D)
CAP, CERM, 2.2 µF, 6.3 V,+/- 20%, X5R, 0201; Manufacturer: MuRata; Polarized: N; CompType: Capacitor; Value: 2.2uF; U/M: EA; Cap_F: 0.0000022; Tolerance_%: 20; VDC_V: 6.3; Value2: 6.3V; TaMin_C: -55; TaMax_C: 85; Cap_Case: 0201; SizeArea_mm2: 0.18; SizeAreaWB_mm2: 2.08; SizeX_mm: 0.6; SizeY_mm: 0.3; SizeZ_mm: 0.4; AEC Category: Q200
signal-integrity model Cap
simulation model Cap
footprint 0201_040
pins: 1, 2

## GRM033R60J273KE01D
designator C?  ValueDisplayed: 0.027µF  (hidden comment: GRM033R60J273KE01D)
CAP, CERM, 0.027 µF, 6.3 V,+/- 10%, X5R, 0201; Manufacturer: MuRata; Polarized: N; CompType: Capacitor; Value: 0.027uF; U/M: EA; Cap_F: 0.000000027; Tolerance_%: 10; VDC_V: 6.3; Value2: 6.3V; TaMin_C: -55; TaMax_C: 85; Cap_Case: 0201; SizeArea_mm2: 0.18; SizeAreaWB_mm2: 2.08; SizeX_mm: 0.6; SizeY_mm: 0.3; SizeZ_mm: 0.26; AEC Category: Q200
signal-integrity model Cap
simulation model Cap
footprint 0201
footprint 0201M
footprint 0201L
footprint 0201_Silk
pins: 1, 2

## GRM033R60J333KE01D
designator C?  ValueDisplayed: 0.033µF  (hidden comment: GRM033R60J333KE01D)
CAP, CERM, 0.033 µF, 6.3 V,+/- 10%, X5R, 0201; Manufacturer: MuRata; Polarized: N; CompType: Capacitor; Value: 0.033uF; U/M: EA; Cap_F: 0.000000033; Tolerance_%: 10; VDC_V: 6.3; Value2: 6.3V; TaMin_C: -55; TaMax_C: 85; Cap_Case: 0201; SizeArea_mm2: 0.18; SizeAreaWB_mm2: 2.08; SizeX_mm: 0.6; SizeY_mm: 0.3; SizeZ_mm: 0.26; AEC Category: Q200
signal-integrity model Cap
simulation model Cap
footprint 0201
footprint 0201M
footprint 0201L
footprint 0201_Silk
pins: 1, 2

## GRM033R60J393KE19D
designator C?  ValueDisplayed: 0.039µF  (hidden comment: GRM033R60J393KE19D)
CAP, CERM, 0.039 µF, 6.3 V,+/- 10%, X5R, 0201; Manufacturer: MuRata; Polarized: N; CompType: Capacitor; Value: 0.039uF; U/M: EA; Cap_F: 0.000000039; Tolerance_%: 10; VDC_V: 6.3; Value2: 6.3V; TaMin_C: -55; TaMax_C: 85; Cap_Case: 0201; SizeArea_mm2: 0.18; SizeAreaWB_mm2: 2.08; SizeX_mm: 0.6; SizeY_mm: 0.3; SizeZ_mm: 0.26; AEC Category: Q200
signal-integrity model Cap
simulation model Cap
footprint 0201
footprint 0201M
footprint 0201L
footprint 0201_Silk
pins: 1, 2

## GRM033R60J473KE19D
designator C?  ValueDisplayed: 0.047µF  (hidden comment: GRM033R60J473KE19D)
CAP, CERM, 0.047 µF, 6.3 V,+/- 10%, X5R, 0201; Manufacturer: MuRata; Polarized: N; CompType: Capacitor; Value: 0.047uF; U/M: EA; Cap_F: 0.000000047; Tolerance_%: 10; VDC_V: 6.3; Value2: 6.3V; TaMin_C: -55; TaMax_C: 85; Cap_Case: 0201; SizeArea_mm2: 0.18; SizeAreaWB_mm2: 2.08; SizeX_mm: 0.6; SizeY_mm: 0.3; SizeZ_mm: 0.26; AEC Category: Q200
signal-integrity model Cap
simulation model Cap
footprint 0201
footprint 0201M
footprint 0201L
footprint 0201_Silk
pins: 1, 2

## GRM033R60J474KE90D
designator C?  ValueDisplayed: 0.47µF  (hidden comment: GRM033R60J474KE90D)
CAP, CERM, 0.47 µF, 6.3 V,+/- 10%, X5R, 0201; Manufacturer: MuRata; Polarized: N; CompType: Capacitor; Value: 0.47uF; U/M: EA; Cap_F: 0.00000047; Tolerance_%: 10; VDC_V: 6.3; Value2: 6.3V; TaMin_C: -55; TaMax_C: 85; Cap_Case: 0201; SizeArea_mm2: 0.18; SizeAreaWB_mm2: 2.08; SizeX_mm: 0.6; SizeY_mm: 0.3; SizeZ_mm: 0.33; AEC Category: Q200
signal-integrity model Cap
simulation model Cap
footprint 0201_033
footprint 0201_033M
footprint 0201_033L
pins: 1, 2

## GRM033R61A103KA01D
designator C?  ValueDisplayed: 0.01µF  (hidden comment: GRM033R61A103KA01D)
CAP, CERM, 0.01 µF, 10 V,+/- 10%, X5R, 0201; Manufacturer: MuRata; Polarized: N; CompType: Capacitor; Value: 0.01uF; U/M: EA; Cap_F: 0.00000001; Tolerance_%: 10; Value2: 10V; TaMin_C: -55; TaMax_C: 85; Cap_Case: 0201; SizeArea_mm2: 0.18; SizeAreaWB_mm2: 2.08; SizeX_mm: 0.6; SizeY_mm: 0.3; SizeZ_mm: 0.26; AEC Category: Q200; Green_Lifecycle: Active; Green_REACh: Passed
signal-integrity model Cap
simulation model Cap
footprint 0201
footprint 0201M
footprint 0201L
footprint 0201_Silk
pins: 1, 2

## GRM033R61A105ME15D
designator C?  ValueDisplayed: 1µF  (hidden comment: GRM033R61A105ME15D)
CAP, CERM, 1 µF, 10 V,+/- 20%, X5R, 0201; Manufacturer: MuRata; Polarized: N; CompType: Capacitor; Value: 1uF; U/M: EA; Cap_F: 0.000001; Tolerance_%: 20; VDC_V: 10; Value2: 10V; TaMin_C: -55; TaMax_C: 85; Cap_Case: 0201; SizeArea_mm2: 0.18; SizeAreaWB_mm2: 2.08; SizeX_mm: 0.6; SizeY_mm: 0.3; SizeZ_mm: 0.26; AEC Category: Q200
signal-integrity model Cap
simulation model Cap
footprint 0201
footprint 0201M
footprint 0201L
footprint 0201_Silk
pins: 1, 2

## GRM033R61A122KA01D
designator C?  ValueDisplayed: 1200pF  (hidden comment: GRM033R61A122KA01D)
CAP, CERM, 1200 pF, 10 V,+/- 10%, X5R, 0201; Manufacturer: MuRata; Polarized: N; CompType: Capacitor; Value: 1200pF; U/M: EA; Cap_F: 0.0000000012; Tolerance_%: 10; Value2: 10V; TaMin_C: -55; TaMax_C: 85; Cap_Case: 0201; SizeArea_mm2: 0.18; SizeAreaWB_mm2: 2.08; SizeX_mm: 0.6; SizeY_mm: 0.3; SizeZ_mm: 0.26; AEC Category: Q200
signal-integrity model Cap
simulation model Cap
footprint 0201
footprint 0201M
footprint 0201L
footprint 0201_Silk
pins: 1, 2

## GRM033R61A152KA01D
designator C?  ValueDisplayed: 1500pF  (hidden comment: GRM033R61A152KA01D)
CAP, CERM, 1500 pF, 10 V,+/- 10%, X5R, 0201; Manufacturer: MuRata; Polarized: N; CompType: Capacitor; Value: 1500pF; U/M: EA; Cap_F: 0.0000000015; Tolerance_%: 10; Value2: 10V; TaMin_C: -55; TaMax_C: 85; Cap_Case: 0201; SizeArea_mm2: 0.18; SizeAreaWB_mm2: 2.08; SizeX_mm: 0.6; SizeY_mm: 0.3; SizeZ_mm: 0.26; AEC Category: Q200
signal-integrity model Cap
simulation model Cap
footprint 0201
footprint 0201M
footprint 0201L
footprint 0201_Silk
pins: 1, 2

## GRM033R61A182KA01D
designator C?  ValueDisplayed: 1800pF  (hidden comment: GRM033R61A182KA01D)
CAP, CERM, 1800 pF, 10 V,+/- 10%, X5R, 0201; Manufacturer: MuRata; Polarized: N; CompType: Capacitor; Value: 1800pF; U/M: EA; Cap_F: 0.0000000018; Tolerance_%: 10; Value2: 10V; TaMin_C: -55; TaMax_C: 85; Cap_Case: 0201; SizeArea_mm2: 0.18; SizeAreaWB_mm2: 2.08; SizeX_mm: 0.6; SizeY_mm: 0.3; SizeZ_mm: 0.26; AEC Category: Q200
signal-integrity model Cap
simulation model Cap
footprint 0201
footprint 0201M
footprint 0201L
footprint 0201_Silk
pins: 1, 2

## GRM033R61A222KA01D
designator C?  ValueDisplayed: 2200pF  (hidden comment: GRM033R61A222KA01D)
CAP, CERM, 2200 pF, 10 V,+/- 10%, X5R, 0201; Manufacturer: MuRata; Polarized: N; CompType: Capacitor; Value: 2200pF; U/M: EA; Cap_F: 0.0000000022; Tolerance_%: 10; Value2: 10V; TaMin_C: -55; TaMax_C: 85; Cap_Case: 0201; SizeArea_mm2: 0.18; SizeAreaWB_mm2: 2.08; SizeX_mm: 0.6; SizeY_mm: 0.3; SizeZ_mm: 0.26; AEC Category: Q200; Green_Lifecycle: Active; Green_REACh: Passed
signal-integrity model Cap
simulation model Cap
footprint 0201
footprint 0201M
footprint 0201L
footprint 0201_Silk
pins: 1, 2

## GRM033R61A272KA01D
designator C?  ValueDisplayed: 2700pF  (hidden comment: GRM033R61A272KA01D)
CAP, CERM, 2700 pF, 10 V,+/- 10%, X5R, 0201; Manufacturer: MuRata; Polarized: N; CompType: Capacitor; Value: 2700pF; U/M: EA; Cap_F: 0.0000000027; Tolerance_%: 10; Value2: 10V; TaMin_C: -55; TaMax_C: 85; Cap_Case: 0201; SizeArea_mm2: 0.18; SizeAreaWB_mm2: 2.08; SizeX_mm: 0.6; SizeY_mm: 0.3; SizeZ_mm: 0.26; AEC Category: Q200
signal-integrity model Cap
simulation model Cap
footprint 0201
footprint 0201M
footprint 0201L
footprint 0201_Silk
pins: 1, 2

## GRM033R61A332KA01D
designator C?  ValueDisplayed: 3300pF  (hidden comment: GRM033R61A332KA01D)
CAP, CERM, 3300 pF, 10 V,+/- 10%, X5R, 0201; Manufacturer: MuRata; Polarized: N; CompType: Capacitor; Value: 3300pF; U/M: EA; Cap_F: 0.0000000033; Tolerance_%: 10; Value2: 10V; TaMin_C: -55; TaMax_C: 85; Cap_Case: 0201; SizeArea_mm2: 0.18; SizeAreaWB_mm2: 2.08; SizeX_mm: 0.6; SizeY_mm: 0.3; SizeZ_mm: 0.26; AEC Category: Q200
signal-integrity model Cap
simulation model Cap
footprint 0201
footprint 0201M
footprint 0201L
footprint 0201_Silk
pins: 1, 2

## GRM033R61A392KA01D
designator C?  ValueDisplayed: 3900pF  (hidden comment: GRM033R61A392KA01D)
CAP, CERM, 3900 pF, 10 V,+/- 10%, X5R, 0201; Manufacturer: MuRata; Polarized: N; CompType: Capacitor; Value: 3900pF; U/M: EA; Cap_F: 0.0000000039; Tolerance_%: 10; Value2: 10V; TaMin_C: -55; TaMax_C: 85; Cap_Case: 0201; SizeArea_mm2: 0.18; SizeAreaWB_mm2: 2.08; SizeX_mm: 0.6; SizeY_mm: 0.3; SizeZ_mm: 0.26; AEC Category: Q200
signal-integrity model Cap
simulation model Cap
footprint 0201
footprint 0201M
footprint 0201L
footprint 0201_Silk
pins: 1, 2

## GRM033R61A472KA01D
designator C?  ValueDisplayed: 4700pF  (hidden comment: GRM033R61A472KA01D)
CAP, CERM, 4700 pF, 10 V,+/- 10%, X5R, 0201; Manufacturer: MuRata; Polarized: N; CompType: Capacitor; Value: 4700pF; U/M: EA; Cap_F: 0.0000000047; Tolerance_%: 10; Value2: 10V; TaMin_C: -55; TaMax_C: 85; Cap_Case: 0201; SizeArea_mm2: 0.18; SizeAreaWB_mm2: 2.08; SizeX_mm: 0.6; SizeY_mm: 0.3; SizeZ_mm: 0.26; AEC Category: Q200; Green_Lifecycle: Active; Green_REACh: Passed
signal-integrity model Cap
simulation model Cap
footprint 0201
footprint 0201M
footprint 0201L
footprint 0201_Silk
pins: 1, 2

## GRM033R61A472MA01D
designator C?  ValueDisplayed: 4700pF  (hidden comment: GRM033R61A472MA01D)
CAP, CERM, 4700 pF, 10 V,+/- 20%, X5R, 0201; Manufacturer: MuRata; Polarized: N; CompType: Capacitor; Value: 4700pF; U/M: EA; Cap_F: 0.0000000047; Tolerance_%: 20; VDC_V: 10; Value2: 10V; TaMin_C: -55; TaMax_C: 85; Cap_Case: 0201; SizeArea_mm2: 0.18; SizeAreaWB_mm2: 2.08; SizeX_mm: 0.6; SizeY_mm: 0.3; SizeZ_mm: 0.33; AEC Category: Q200
signal-integrity model Cap
simulation model Cap
footprint 0201_033
footprint 0201_033M
footprint 0201_033L
pins: 1, 2

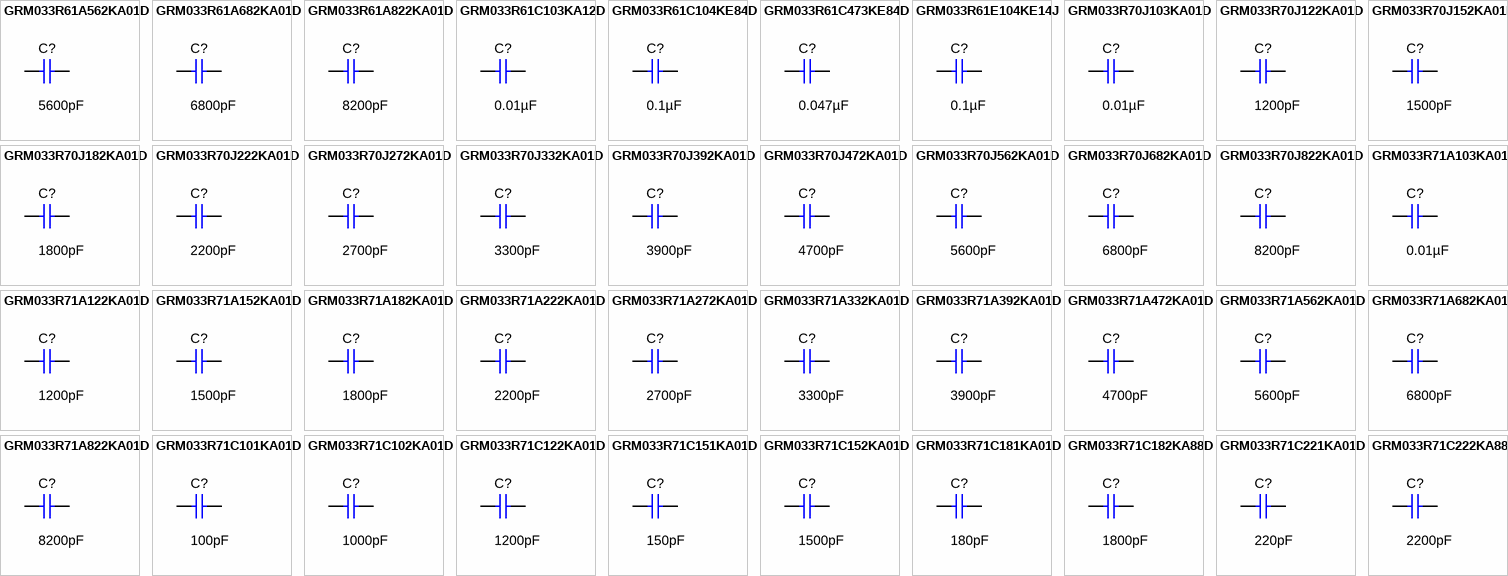
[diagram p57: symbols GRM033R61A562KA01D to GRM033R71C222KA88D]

## GRM033R61A562KA01D
designator C?  ValueDisplayed: 5600pF  (hidden comment: GRM033R61A562KA01D)
CAP, CERM, 5600 pF, 10 V,+/- 10%, X5R, 0201; Manufacturer: MuRata; Polarized: N; CompType: Capacitor; Value: 5600pF; U/M: EA; Cap_F: 0.0000000056; Tolerance_%: 10; Value2: 10V; TaMin_C: -55; TaMax_C: 85; Cap_Case: 0201; SizeArea_mm2: 0.18; SizeAreaWB_mm2: 2.08; SizeX_mm: 0.6; SizeY_mm: 0.3; SizeZ_mm: 0.26; AEC Category: Q200
signal-integrity model Cap
simulation model Cap
footprint 0201
footprint 0201M
footprint 0201L
footprint 0201_Silk
pins: 1, 2

## GRM033R61A682KA01D
designator C?  ValueDisplayed: 6800pF  (hidden comment: GRM033R61A682KA01D)
CAP, CERM, 6800 pF, 10 V,+/- 10%, X5R, 0201; Manufacturer: MuRata; Polarized: N; CompType: Capacitor; Value: 6800pF; U/M: EA; Cap_F: 0.0000000068; Tolerance_%: 10; Value2: 10V; TaMin_C: -55; TaMax_C: 85; Cap_Case: 0201; SizeArea_mm2: 0.18; SizeAreaWB_mm2: 2.08; SizeX_mm: 0.6; SizeY_mm: 0.3; SizeZ_mm: 0.26; AEC Category: Q200
signal-integrity model Cap
simulation model Cap
footprint 0201
footprint 0201M
footprint 0201L
footprint 0201_Silk
pins: 1, 2

## GRM033R61A822KA01D
designator C?  ValueDisplayed: 8200pF  (hidden comment: GRM033R61A822KA01D)
CAP, CERM, 8200 pF, 10 V,+/- 10%, X5R, 0201; Manufacturer: MuRata; Polarized: N; CompType: Capacitor; Value: 8200pF; U/M: EA; Cap_F: 0.0000000082; Tolerance_%: 10; Value2: 10V; TaMin_C: -55; TaMax_C: 85; Cap_Case: 0201; SizeArea_mm2: 0.18; SizeAreaWB_mm2: 2.08; SizeX_mm: 0.6; SizeY_mm: 0.3; SizeZ_mm: 0.26; AEC Category: Q200
signal-integrity model Cap
simulation model Cap
footprint 0201
footprint 0201M
footprint 0201L
footprint 0201_Silk
pins: 1, 2

## GRM033R61C103KA12D
designator C?  ValueDisplayed: 0.01µF  (hidden comment: GRM033R61C103KA12D)
CAP, CERM, 0.01 µF, 16 V,+/- 10%, X5R, 0201; Manufacturer: MuRata; Polarized: N; CompType: Capacitor; Value: 0.01uF; U/M: EA; Cap_F: 0.00000001; Tolerance_%: 10; VDC_V: 16; Value2: 16V; TaMin_C: -55; TaMax_C: 85; Cap_Case: 0201; SizeArea_mm2: 0.18; SizeAreaWB_mm2: 2.08; SizeX_mm: 0.6; SizeY_mm: 0.3; SizeZ_mm: 0.33; AEC Category: Q200
signal-integrity model Cap
simulation model Cap
footprint 0201_033
footprint 0201_033M
footprint 0201_033L
pins: 1, 2

## GRM033R61C104KE84D
designator C?  ValueDisplayed: 0.1µF  (hidden comment: GRM033R61C104KE84D)
CAP, CERM, 0.1 µF, 16 V,+/- 10%, X5R, 0201; Manufacturer: MuRata; Polarized: N; CompType: Capacitor; Value: 0.1uF; U/M: EA; Cap_F: 0.0000001; Tolerance_%: 10; VDC_V: 16; Value2: 16V; TaMin_C: -55; TaMax_C: 85; Cap_Case: 0201; SizeArea_mm2: 0.18; SizeAreaWB_mm2: 2.08; SizeX_mm: 0.6; SizeY_mm: 0.3; SizeZ_mm: 0.33; AEC Category: Q200
signal-integrity model Cap
simulation model Cap
footprint 0201_033
footprint 0201_033M
footprint 0201_033L
pins: 1, 2

## GRM033R61C473KE84D
designator C?  ValueDisplayed: 0.047µF  (hidden comment: GRM033R61C473KE84D)
CAP, CERM, 0.047 µF, 16 V,+/- 10%, X5R, 0201; Manufacturer: MuRata; Polarized: N; CompType: Capacitor; Value: 0.047uF; U/M: EA; Cap_F: 0.000000047; Tolerance_%: 10; VDC_V: 16; Value2: 16V; TaMin_C: -55; TaMax_C: 85; Cap_Case: 0201; SizeArea_mm2: 0.18; SizeAreaWB_mm2: 2.08; SizeX_mm: 0.6; SizeY_mm: 0.3; SizeZ_mm: 0.33; AEC Category: Q200; Green_Lifecycle: Active; Green_REACh: Passed
signal-integrity model Cap
simulation model Cap
footprint 0201_033
footprint 0201_033M
footprint 0201_033L
pins: 1, 2

## GRM033R61E104KE14J
designator C?  ValueDisplayed: 0.1µF  (hidden comment: GRM033R61E104KE14J)
CAP, CERM, 0.1 µF, 25 V,+/- 10%, X5R, 0201; Manufacturer: MuRata; Polarized: N; CompType: Capacitor; Value: 0.1uF; U/M: EA; Cap_F: 0.0000001; Tolerance_%: 10; VDC_V: 25; Value2: 25V; TaMin_C: -55; TaMax_C: 85; Cap_Case: 0201; SizeArea_mm2: 0.18; SizeAreaWB_mm2: 2.08; SizeX_mm: 0.6; SizeY_mm: 0.3; SizeZ_mm: 0.33; AEC Category: Q200; Green_Lifecycle: Active; Green_REACh: Passed
signal-integrity model Cap
simulation model Cap
footprint 0201_033
footprint 0201_033M
footprint 0201_033L
pins: 1, 2

## GRM033R70J103KA01D
designator C?  ValueDisplayed: 0.01µF  (hidden comment: GRM033R70J103KA01D)
CAP, CERM, 0.01 µF, 6.3 V,+/- 10%, X7R, 0201; Manufacturer: MuRata; Polarized: N; CompType: Capacitor; Value: 0.01uF; U/M: EA; Cap_F: 0.00000001; Tolerance_%: 10; VDC_V: 6.3; Value2: 6.3V; TaMin_C: -55; TaMax_C: 125; Cap_Case: 0201; SizeArea_mm2: 0.18; SizeAreaWB_mm2: 2.08; SizeX_mm: 0.6; SizeY_mm: 0.3; SizeZ_mm: 0.26; AEC Category: Q200
signal-integrity model Cap
simulation model Cap
footprint 0201
footprint 0201M
footprint 0201L
footprint 0201_Silk
pins: 1, 2

## GRM033R70J122KA01D
designator C?  ValueDisplayed: 1200pF  (hidden comment: GRM033R70J122KA01D)
CAP, CERM, 1200 pF, 6.3 V,+/- 10%, X7R, 0201; Manufacturer: MuRata; Polarized: N; CompType: Capacitor; Value: 1200pF; U/M: EA; Cap_F: 0.0000000012; Tolerance_%: 10; VDC_V: 6.3; Value2: 6.3V; TaMin_C: -55; TaMax_C: 125; Cap_Case: 0201; SizeArea_mm2: 0.18; SizeAreaWB_mm2: 2.08; SizeX_mm: 0.6; SizeY_mm: 0.3; SizeZ_mm: 0.26; AEC Category: Q200
signal-integrity model Cap
simulation model Cap
footprint 0201
footprint 0201M
footprint 0201L
footprint 0201_Silk
pins: 1, 2

## GRM033R70J152KA01D
designator C?  ValueDisplayed: 1500pF  (hidden comment: GRM033R70J152KA01D)
CAP, CERM, 1500 pF, 6.3 V,+/- 10%, X7R, 0201; Manufacturer: MuRata; Polarized: N; CompType: Capacitor; Value: 1500pF; U/M: EA; Cap_F: 0.0000000015; Tolerance_%: 10; VDC_V: 6.3; Value2: 6.3V; TaMin_C: -55; TaMax_C: 125; Cap_Case: 0201; SizeArea_mm2: 0.18; SizeAreaWB_mm2: 2.08; SizeX_mm: 0.6; SizeY_mm: 0.3; SizeZ_mm: 0.26; AEC Category: Q200
signal-integrity model Cap
simulation model Cap
footprint 0201
footprint 0201M
footprint 0201L
footprint 0201_Silk
pins: 1, 2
